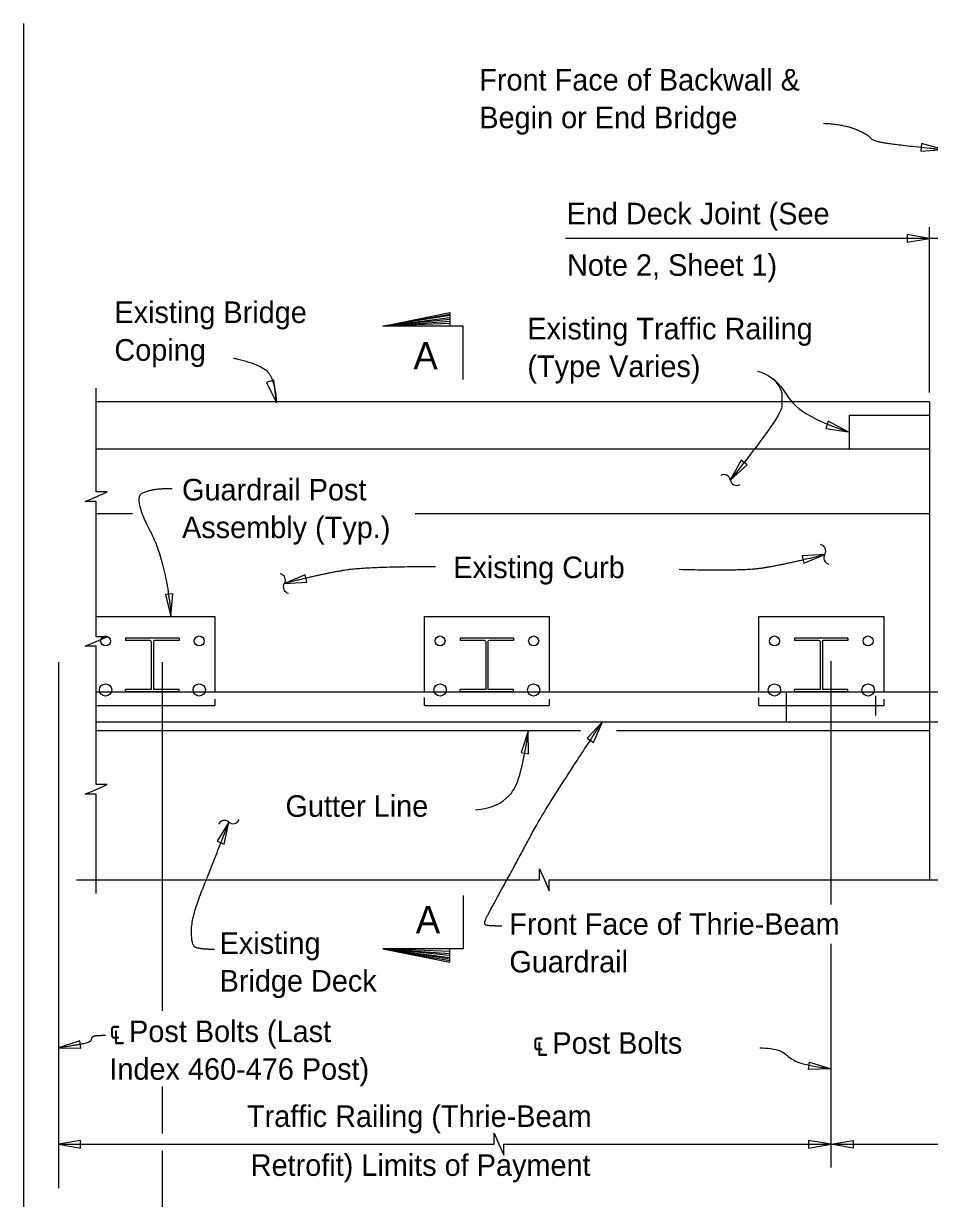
# Model space of a CAD drawing. Extents: x 21526.6 to 21598.7, y 56118.1 to 56155.9.
# Drawn here: x 21545.72 to 21554.18, y 56142.28 to 56153.26 of the extents above; entities that cross this region are included whole.
import ezdxf

# ---------------------------------------------------------------- set-up
doc = ezdxf.new("R2010")
doc.units = 0
for name, color, linetype in [('AdhocPoint_dp', 7, 'Continuous'), ('Border', 7, 'Continuous'), ('Patterning', 7, 'Continuous'), ('PlotBorder_dp', 7, 'Continuous'), ('SheetBorder_dp', 7, 'Continuous'), ('TextMisc', 7, 'Continuous')]:
    doc.layers.add(name, color=color, linetype=linetype)

msp = doc.modelspace()

# ---------------------------------------------------------------- linework, layer by layer
at = {"layer": 'AdhocPoint_dp'}
for p, q in [((21554.182, 56149.72), (21546.396, 56149.72)), ((21554.182, 56149.722), (21554.182, 56145.254)), ((21553.432, 56149.595), (21554.182, 56149.595)), ((21546.396, 56149.282), (21554.182, 56149.282)), ((21546.396, 56148.678), (21546.735, 56148.678)), ((21549.378, 56148.678), (21554.182, 56148.678)), ((21546.395, 56146.648), (21550.921, 56146.648)), ((21551.257, 56146.648), (21554.182, 56146.648))]:
    msp.add_line(p, q, dxfattribs=at)
msp.add_lwpolyline([(21553.432, 56149.595), (21553.432, 56149.282)], dxfattribs=at)
at = {"layer": 'Patterning'}
for p, q in [((21546.042, 56147.287), (21546.042, 56142.373)), ((21547.015, 56144.029), (21547.015, 56147.287)), ((21547.015, 56142.884), (21547.015, 56143.322)), ((21547.015, 56139.153), (21547.015, 56142.721))]:
    msp.add_line(p, q, dxfattribs=at)
at = {"layer": 'PlotBorder_dp'}
for p, q in [((21545.716, 56153.256), (21545.716, 56127.317)), ((21554.182, 56149.808), (21554.182, 56151.352)), ((21554.69, 56151.248), (21550.781, 56151.248)), ((21549.076, 56150.429), (21549.701, 56150.539)), ((21549.701, 56150.526), (21549.076, 56150.429)), ((21549.076, 56150.429), (21549.701, 56150.509)), ((21549.701, 56150.491), (21549.076, 56150.429)), ((21549.076, 56150.429), (21549.701, 56150.473)), ((21549.701, 56150.453), (21549.076, 56150.429)), ((21553.263, 56145.023), (21553.263, 56147.297)), ((21549.701, 56144.586), (21549.076, 56144.609)), ((21549.076, 56144.609), (21549.701, 56144.566)), ((21549.701, 56144.547), (21549.076, 56144.609)), ((21549.076, 56144.609), (21549.701, 56144.529)), ((21549.701, 56144.512), (21549.076, 56144.609)), ((21549.076, 56144.609), (21549.701, 56144.499)), ((21553.263, 56142.567), (21553.263, 56144.657))]:
    msp.add_line(p, q, dxfattribs=at)
for points in [[(21554.314, 56152.078), (21554.11, 56152.134), (21554.103, 56152.064)], [(21554.182, 56151.248), (21553.974, 56151.283), (21553.974, 56151.212)], [(21548.081, 56149.712), (21548.056, 56149.922), (21547.988, 56149.902)], [(21553.424, 56149.441), (21553.237, 56149.539), (21553.215, 56149.472)], [(21552.322, 56148.989), (21552.479, 56149.131), (21552.424, 56149.175)], [(21553.205, 56148.295), (21552.994, 56148.282), (21553.01, 56148.213)], [(21548.154, 56148.023), (21548.365, 56148.036), (21548.349, 56148.105)], [(21547.094, 56147.715), (21547.113, 56147.926), (21547.043, 56147.92)], [(21551.128, 56146.731), (21550.983, 56146.577), (21551.042, 56146.538)], [(21550.434, 56146.643), (21550.368, 56146.443), (21550.437, 56146.432)], [(21547.635, 56145.794), (21547.525, 56145.614), (21547.591, 56145.588)], [(21546.042, 56143.683), (21546.253, 56143.68), (21546.242, 56143.75)], [(21553.264, 56143.488), (21553.053, 56143.482), (21553.063, 56143.552)], [(21546.042, 56142.784), (21546.25, 56142.748), (21546.25, 56142.819)], [(21553.263, 56142.784), (21553.054, 56142.819), (21553.054, 56142.748)], [(21553.263, 56142.784), (21553.471, 56142.819), (21553.471, 56142.748)]]:
    msp.add_lwpolyline(points, close=True, dxfattribs=at)
for points in [[(21549.826, 56149.929), (21549.826, 56150.429), (21549.076, 56150.429), (21549.701, 56150.554), (21549.701, 56150.429)], [(21546.396, 56148.32), (21546.396, 56148.789), (21546.292, 56148.789), (21546.396, 56148.834), (21546.499, 56148.879), (21546.396, 56148.879), (21546.396, 56149.848)], [(21546.396, 56146.573), (21546.396, 56147.436), (21546.292, 56147.436), (21546.396, 56147.481), (21546.499, 56147.526), (21546.396, 56147.526), (21546.396, 56148.32)], [(21546.396, 56145.126), (21546.396, 56146.054), (21546.292, 56146.054), (21546.396, 56146.099), (21546.499, 56146.144), (21546.396, 56146.144), (21546.396, 56147.017)], [(21546.211, 56145.254), (21550.54, 56145.254), (21550.54, 56145.357), (21550.585, 56145.254), (21550.63, 56145.15), (21550.63, 56145.254), (21553.591, 56145.254)], [(21553.591, 56145.254), (21558.041, 56145.254), (21558.041, 56145.357), (21558.086, 56145.254), (21558.131, 56145.15), (21558.131, 56145.254), (21560.824, 56145.254)], [(21549.826, 56145.109), (21549.826, 56144.609), (21549.076, 56144.609), (21549.701, 56144.484), (21549.701, 56144.609)], [(21546.042, 56142.784), (21550.114, 56142.784), (21550.114, 56142.887), (21550.159, 56142.784), (21550.204, 56142.68), (21550.204, 56142.784), (21562.137, 56142.784)]]:
    msp.add_lwpolyline(points, dxfattribs=at)
for centre, start, end in [((21552.263, 56148.981), 8.6098, 120.3371), ((21552.381, 56148.999), 188.6098, 300.3371), ((21553.154, 56148.328), 327.2252, 78.9524), ((21553.255, 56148.263), 147.2252, 258.9524), ((21548.104, 56148.055), 327.2252, 78.9524), ((21548.204, 56147.99), 147.2252, 258.9524), ((21547.594, 56145.75), 47.1839, 158.9112), ((21547.675, 56145.838), 227.1839, 338.9112)]:
    msp.add_arc(centre, 0.0596, start, end, dxfattribs=at)
for points, degree in [([(21553.192, 56152.323), (21553.377, 56152.316), (21553.614, 56152.217), (21553.647, 56152.158), (21553.918, 56152.118), (21554.314, 56152.078)], 2), ([(21547.678, 56150.129), (21547.874, 56150.087), (21548.063, 56149.967), (21548.081, 56149.712)], 2), ([(21552.577, 56150.007), (21552.668, 56149.983), (21552.836, 56149.869), (21552.933, 56149.6), (21553.424, 56149.441)], 3), ([(21552.719, 56149.939), (21552.802, 56149.846), (21552.802, 56149.749), (21552.802, 56149.595), (21552.322, 56148.989)], 2), ([(21547.105, 56148.909), (21546.911, 56148.909), (21546.739, 56148.823), (21547.054, 56148.217), (21547.094, 56147.715)], 2), ([(21551.844, 56148.156), (21552.426, 56148.139), (21552.831, 56148.201), (21553.205, 56148.295)], 2), ([(21549.567, 56148.179), (21548.932, 56148.179), (21548.527, 56148.117), (21548.154, 56148.023)], 2), ([(21550.187, 56144.822), (21550.074, 56144.822), (21550.01, 56144.837), (21550.081, 56144.975), (21550.364, 56145.491), (21550.601, 56145.937), (21551.128, 56146.731)], 2), ([(21549.94, 56145.907), (21550.09, 56145.919), (21550.275, 56146.017), (21550.365, 56146.198), (21550.435, 56146.643)], 3), ([(21547.501, 56144.604), (21547.349, 56144.604), (21547.286, 56144.65), (21547.286, 56144.908), (21547.494, 56145.424), (21547.635, 56145.794)], 2), ([(21546.484, 56143.799), (21546.418, 56143.798), (21546.354, 56143.792), (21546.345, 56143.735), (21546.219, 56143.711), (21546.042, 56143.683)], 2), ([(21552.599, 56143.684), (21552.666, 56143.683), (21552.812, 56143.67), (21552.888, 56143.564), (21553.03, 56143.521), (21553.264, 56143.488)], 3)]:
    msp.add_open_spline(points, degree=degree, dxfattribs=at)
at = {"layer": 'SheetBorder_dp'}
for p, q in [((21552.848, 56146.732), (21552.848, 56147.012)), ((21552.848, 56147.012), (21566.396, 56147.012)), ((21553.682, 56146.789), (21553.682, 56146.974)), ((21552.848, 56146.732), (21566.234, 56146.732))]:
    msp.add_line(p, q, dxfattribs=at)
for points in [[(21546.396, 56146.882), (21547.505, 56146.882)], [(21549.463, 56146.882), (21550.63, 56146.882)], [(21552.588, 56146.882), (21553.755, 56146.882)]]:
    msp.add_lwpolyline(points, dxfattribs=at)
at = {"layer": 'TextMisc'}
for p, q in [((21547.171, 56147.512), (21546.671, 56147.512)), ((21546.671, 56147.512), (21546.671, 56147.491)), ((21546.9, 56147.491), (21546.671, 56147.491)), ((21546.911, 56147.481), (21546.911, 56147.033)), ((21546.932, 56147.481), (21546.932, 56147.033)), ((21547.171, 56147.491), (21546.942, 56147.491)), ((21547.171, 56147.512), (21547.171, 56147.491)), ((21550.296, 56147.512), (21549.796, 56147.512)), ((21549.796, 56147.512), (21549.796, 56147.491)), ((21550.025, 56147.491), (21549.796, 56147.491)), ((21550.036, 56147.481), (21550.036, 56147.033)), ((21550.057, 56147.481), (21550.057, 56147.033)), ((21550.296, 56147.491), (21550.067, 56147.491)), ((21550.296, 56147.512), (21550.296, 56147.491)), ((21553.421, 56147.512), (21552.921, 56147.512)), ((21552.921, 56147.512), (21552.921, 56147.491)), ((21553.15, 56147.491), (21552.921, 56147.491)), ((21553.161, 56147.481), (21553.161, 56147.033)), ((21553.182, 56147.481), (21553.182, 56147.033)), ((21553.421, 56147.491), (21553.192, 56147.491)), ((21553.421, 56147.512), (21553.421, 56147.491)), ((21546.395, 56147.012), (21552.848, 56147.012)), ((21546.911, 56147.033), (21546.671, 56147.033)), ((21546.671, 56147.012), (21546.671, 56147.033)), ((21547.171, 56147.012), (21546.671, 56147.012)), ((21547.171, 56147.033), (21546.932, 56147.033)), ((21547.171, 56147.012), (21547.171, 56147.033)), ((21550.036, 56147.033), (21549.796, 56147.033)), ((21549.796, 56147.012), (21549.796, 56147.033)), ((21550.296, 56147.012), (21549.796, 56147.012)), ((21550.296, 56147.033), (21550.057, 56147.033)), ((21550.296, 56147.012), (21550.296, 56147.033)), ((21553.161, 56147.033), (21552.921, 56147.033)), ((21552.921, 56147.012), (21552.921, 56147.033)), ((21553.421, 56147.012), (21552.921, 56147.012)), ((21553.421, 56147.033), (21553.182, 56147.033)), ((21553.421, 56147.012), (21553.421, 56147.033)), ((21546.395, 56146.732), (21552.848, 56146.732))]:
    msp.add_line(p, q, dxfattribs=at)
for points in [[(21546.396, 56147.715), (21547.505, 56147.715), (21547.505, 56147.017)], [(21549.463, 56147.017), (21549.463, 56147.715), (21550.63, 56147.715), (21550.63, 56147.01)], [(21552.588, 56147.017), (21552.588, 56147.715), (21553.755, 56147.715), (21553.755, 56147.01)], [(21547.505, 56146.943), (21547.505, 56146.882)], [(21549.463, 56146.882), (21549.463, 56146.959)], [(21550.63, 56146.943), (21550.63, 56146.882)], [(21552.588, 56146.882), (21552.588, 56146.959)], [(21553.755, 56146.943), (21553.755, 56146.882)]]:
    msp.add_lwpolyline(points, dxfattribs=at)
for centre, radius in [((21546.484, 56147.486), 0.0469), ((21547.359, 56147.486), 0.0469), ((21549.609, 56147.486), 0.0469), ((21550.484, 56147.486), 0.0469), ((21552.734, 56147.486), 0.0469), ((21553.609, 56147.486), 0.0469), ((21546.484, 56147.028), 0.0573), ((21547.359, 56147.028), 0.0573), ((21549.609, 56147.028), 0.0573), ((21550.484, 56147.028), 0.0573), ((21552.734, 56147.028), 0.0573), ((21553.609, 56147.028), 0.0573)]:
    msp.add_circle(centre, radius, dxfattribs=at)
for centre, start, end in [((21546.9, 56147.481), 0, 90), ((21546.942, 56147.481), 90, 180), ((21550.025, 56147.481), 0, 90), ((21550.067, 56147.481), 90, 180), ((21553.15, 56147.481), 0, 90), ((21553.192, 56147.481), 90, 180)]:
    msp.add_arc(centre, 0.0104, start, end, dxfattribs=at)

# ---------------------------------------------------------------- texts
at = {"layer": 'Border'}
for s, height, p in [('End Deck Joint (See', 0.2016, (21550.792, 56151.379)), ('Note 2, Sheet 1)', 0.2016, (21550.796, 56150.898)), ('A', 0.256, (21549.36, 56150.023)), ('Existing Curb', 0.2016, (21549.732, 56148.073)), ('Gutter Line', 0.2016, (21548.165, 56145.843)), ('A', 0.256, (21549.382, 56144.754)), ('℄ Post Bolts', 0.2016, (21550.475, 56143.629))]:
    msp.add_text(s, height=height, dxfattribs=at).set_placement(p)
at = {"layer": 'PlotBorder_dp'}
for s, p in [('Front Face of Backwall &', (21549.976, 56152.629)), ('Begin or End Bridge', (21549.976, 56152.277)), ('Existing Bridge ', (21546.566, 56150.457)), ('Existing Traffic Railing', (21550.425, 56150.304)), ('Coping ', (21546.566, 56150.105)), ('(Type Varies)', (21550.425, 56149.952)), ('Guardrail Post ', (21547.198, 56148.799)), ('Assembly (Typ.)', (21547.198, 56148.447)), ('Front Face of Thrie-Beam ', (21550.257, 56144.741)), ('Existing ', (21547.549, 56144.562)), ('Guardrail', (21550.257, 56144.389)), ('Bridge Deck', (21547.549, 56144.21)), ('℄ Post Bolts (Last ', (21546.519, 56143.738)), ('Index 460-476 Post)', (21546.519, 56143.386)), ('Traffic Railing (Thrie-Beam ', (21547.805, 56142.945)), ('Retrofit) Limits of Payment', (21547.84, 56142.488))]:
    msp.add_text(s, height=0.2016, dxfattribs=at).set_placement(p)

doc.saveas('drawing.dxf')
